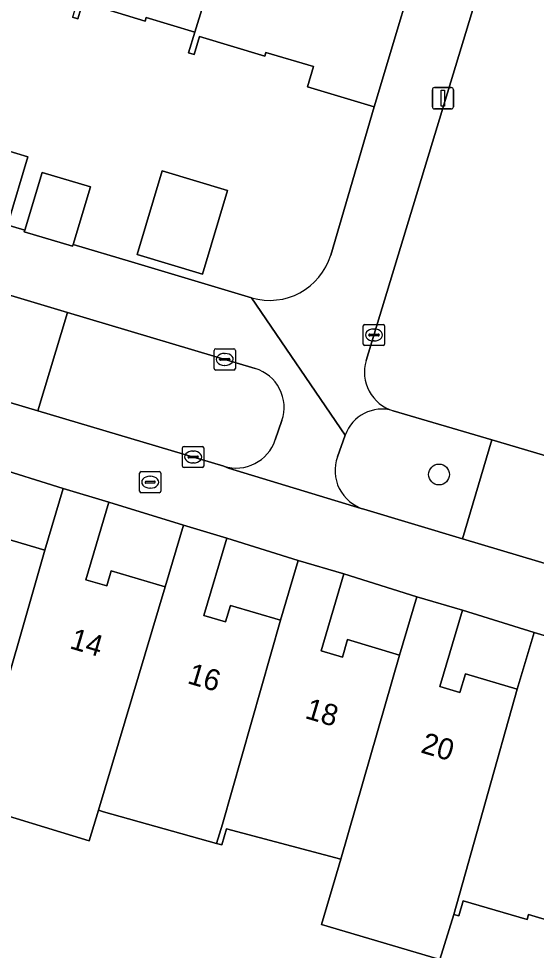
# Model space of a CAD drawing. Extents: x 162184 to 163154, y 385507 to 386516.
# Drawn here: x 162667.22 to 162691.57, y 386180.64 to 386224.51 of the extents above; entities that cross this region are included whole.
import ezdxf

# ---------------------------------------------------------------- set-up
doc = ezdxf.new("R2010")
doc.units = 0
for name, color, linetype in [('IMGEO_Boom', 7, 'Continuous'), ('IMGEO_Brandkraan', 7, 'Continuous'), ('IMGEO_Erf', 7, 'Continuous'), ('IMGEO_Groenvoorziening', 7, 'Continuous'), ('IMGEO_Kolk', 7, 'Continuous'), ('IMGEO_Lichtmast', 7, 'Continuous'), ('IMGEO_Muur', 7, 'Continuous'), ('IMGEO_Pand', 7, 'Continuous'), ('IMGEO_Pand_nummerreeks', 7, 'Continuous'), ('IMGEO_Rijbaan_lokaal_open', 7, 'Continuous'), ('IMGEO_Voetpad_open', 7, 'Continuous')]:
    doc.layers.add(name, color=color, linetype=linetype)

msp = doc.modelspace()

# ---------------------------------------------------------------- linework, layer by layer
at = {"layer": 'IMGEO_Boom'}
msp.add_circle((162686.993, 386203.046), 0.489, dxfattribs=at)
at = {"layer": 'IMGEO_Brandkraan'}
for p, q in [((162672.907, 386202.259), (162672.907, 386203.111)), ((162672.982, 386203.185), (162673.834, 386203.185)), ((162673.395, 386202.965), (162673.42, 386202.965)), ((162673.908, 386203.111), (162673.908, 386202.259)), ((162673.166, 386202.679), (162673.166, 386202.691)), ((162673.604, 386202.642), (162673.206, 386202.642)), ((162673.209, 386202.728), (162673.607, 386202.728)), ((162673.418, 386202.405), (162673.393, 386202.405)), ((162673.65, 386202.691), (162673.65, 386202.679)), ((162673.834, 386202.185), (162672.982, 386202.185))]:
    msp.add_line(p, q, dxfattribs=at)
for points in [[(162672.907, 386202.259), (162672.907, 386203.111)], [(162672.982, 386203.185), (162673.834, 386203.185)], [(162673.908, 386203.111), (162673.908, 386202.259)], [(162673.834, 386202.185), (162672.982, 386202.185)]]:
    msp.add_lwpolyline(points, dxfattribs=at)
for centre, radius, start, end in [((162672.984, 386203.109), 0.0765, 91.552, 178.448), ((162672.984, 386203.109), 0.0765, 91.552, 178.448), ((162673.832, 386203.109), 0.0765, 1.552, 88.448), ((162673.832, 386203.109), 0.0765, 1.552, 88.448), ((162673.206, 386202.688), 0.0403, 85.8775, 175.7526), ((162673.203, 386202.678), 0.0366, 178.938, 274.7102), ((162673.607, 386202.685), 0.043, 264.8664, 352.4533), ((162673.611, 386202.69), 0.0386, 1.7309, 96.639), ((162672.984, 386202.261), 0.0765, 181.552, 268.448), ((162672.984, 386202.261), 0.0765, 181.552, 268.448), ((162673.832, 386202.261), 0.0765, 271.552, 358.448), ((162673.832, 386202.261), 0.0765, 271.552, 358.448)]:
    msp.add_arc(centre, radius, start, end, dxfattribs=at)
for centre, major_axis, ratio, start_param, end_param in [((162673.394, 386202.685), (-0.387, 0.002), 0.722429, 4.712389, 7.853982), ((162673.419, 386202.685), (-0.39, 0.002), 0.717154, 1.570796, 4.712389)]:
    msp.add_ellipse(centre, major_axis=major_axis, ratio=ratio, start_param=start_param, end_param=end_param, dxfattribs=at)
at = {"layer": 'IMGEO_Erf'}
for points in [[(162609.673, 386231.789), (162618.261, 386229.221), (162619.516, 386233.282), (162623.27, 386232.189), (162622.043, 386228.107), (162647.252, 386220.589), (162647.783, 386222.491), (162651.141, 386221.554), (162650.593, 386219.592), (162667.509, 386214.547), (162668.325, 386217.27), (162670.595, 386216.59), (162669.78, 386213.87), (162672.525, 386213.051), (162678.17, 386211.368)], [(162681.897, 386213.378), (162683.948, 386220.358), (162680.8, 386221.3), (162681.084, 386222.247), (162678.853, 386222.915), (162678.799, 386222.737), (162675.72, 386223.659), (162675.469, 386222.822), (162675.215, 386222.898), (162675.507, 386223.871), (162673.224, 386224.554), (162673.176, 386224.394), (162670.232, 386225.275), (162669.999, 386224.496), (162669.754, 386224.569)], [(162693.133, 386180.547), (162693.464, 386181.665), (162691.204, 386182.336), (162691.132, 386182.093), (162688.131, 386182.984), (162687.918, 386182.267), (162687.686, 386182.336), (162687.034, 386180.211), (162681.466, 386181.862), (162682.092, 386183.975), (162682.375, 386184.93), (162676.996, 386186.36), (162676.773, 386185.611), (162676.533, 386185.682), (162671.213, 386187.169), (162670.97, 386187.241), (162670.543, 386185.797), (162664.983, 386187.492)]]:
    msp.add_lwpolyline(points, dxfattribs=at)
for points in [[(162666.725, 386214.895), (162664.116, 386215.676), (162665.047, 386218.788), (162667.657, 386218.007)], [(162675.869, 386212.483), (162672.798, 386213.402), (162673.978, 386217.342), (162677.049, 386216.423)], [(162665.894, 386203.459), (162664.788, 386199.732), (162665.828, 386199.424), (162666.058, 386200.198), (162668.454, 386199.488), (162669.313, 386202.384)], [(162671.463, 386201.746), (162670.38, 386198.094), (162671.367, 386197.801), (162671.577, 386198.51), (162674.12, 386197.756), (162674.98, 386200.654)], [(162677.007, 386200.053), (162675.926, 386196.412), (162676.95, 386196.108), (162677.18, 386196.882), (162679.539, 386196.182), (162680.375, 386199.002)], [(162682.52, 386198.365), (162681.444, 386194.738), (162682.448, 386194.44), (162682.695, 386195.273), (162685.141, 386194.547), (162685.957, 386197.294)], [(162688.098, 386196.659), (162687.03, 386193.059), (162687.972, 386192.78), (162688.232, 386193.656), (162690.669, 386192.933), (162691.463, 386195.604)]]:
    msp.add_lwpolyline(points, close=True, dxfattribs=at)
msp.add_arc((162679.025, 386214.243), 2.999, 253.4323, 343.2444, dxfattribs=at)
at = {"layer": 'IMGEO_Groenvoorziening'}
for points in [[(162669.521, 386210.679), (162651.203, 386216.166), (162643.529, 386218.419), (162642.14, 386213.753), (162651.146, 386211.101), (162668.123, 386206.04)], [(162700.454, 386196.325), (162701.908, 386200.996), (162701.811, 386201.027), (162689.472, 386204.679), (162688.104, 386200.024)]]:
    msp.add_lwpolyline(points, close=True, dxfattribs=at)
for points in [[(162678.347, 386208.035), (162669.521, 386210.679), (162668.123, 386206.04), (162676.868, 386203.433)], [(162683.454, 386201.416), (162688.104, 386200.024), (162689.472, 386204.679), (162684.836, 386206.051)], [(162679.292, 386204.673), (162679.604, 386205.587)], [(162682.581, 386204.898), (162682.213, 386203.881)]]:
    msp.add_lwpolyline(points, dxfattribs=at)
for centre, radius, start, end in [((162677.794, 386206.204), 1.913, 341.1762, 73.183), ((162684.318, 386204.282), 1.843, 73.6911, 160.471), ((162677.44, 386205.304), 1.956, 252.9905, 341.1937), ((162683.999, 386203.235), 1.899, 160.133, 253.3127)]:
    msp.add_arc(centre, radius, start, end, dxfattribs=at)
at = {"layer": 'IMGEO_Kolk'}
for p, q in [((162683.432, 386209.188), (162683.432, 386210.04)), ((162683.507, 386210.114), (162684.359, 386210.114)), ((162683.92, 386209.894), (162683.945, 386209.894)), ((162684.433, 386210.04), (162684.433, 386209.188)), ((162683.691, 386209.608), (162683.691, 386209.62)), ((162684.129, 386209.571), (162683.731, 386209.571)), ((162683.734, 386209.657), (162684.132, 386209.657)), ((162684.175, 386209.62), (162684.175, 386209.608)), ((162676.489, 386208.965), (162677.341, 386208.965)), ((162684.359, 386209.114), (162683.507, 386209.114)), ((162683.943, 386209.334), (162683.918, 386209.334)), ((162676.414, 386208.039), (162676.414, 386208.891)), ((162676.673, 386208.459), (162676.673, 386208.471)), ((162676.716, 386208.508), (162677.114, 386208.508)), ((162676.902, 386208.745), (162676.927, 386208.745)), ((162677.157, 386208.471), (162677.157, 386208.459)), ((162677.415, 386208.891), (162677.415, 386208.039)), ((162677.111, 386208.422), (162676.713, 386208.422)), ((162676.925, 386208.185), (162676.9, 386208.185)), ((162677.341, 386207.965), (162676.489, 386207.965)), ((162674.928, 386203.444), (162674.928, 386204.296)), ((162675.003, 386204.37), (162675.855, 386204.37)), ((162675.416, 386204.15), (162675.441, 386204.15)), ((162675.929, 386204.296), (162675.929, 386203.444)), ((162675.187, 386203.864), (162675.187, 386203.876)), ((162675.625, 386203.827), (162675.227, 386203.827)), ((162675.23, 386203.913), (162675.628, 386203.913)), ((162675.671, 386203.876), (162675.671, 386203.864)), ((162675.855, 386203.37), (162675.003, 386203.37)), ((162675.439, 386203.59), (162675.414, 386203.59))]:
    msp.add_line(p, q, dxfattribs=at)
for points in [[(162683.432, 386209.188), (162683.432, 386210.04)], [(162683.507, 386210.114), (162684.359, 386210.114)], [(162684.433, 386210.04), (162684.433, 386209.188)], [(162676.489, 386208.965), (162677.341, 386208.965)], [(162684.359, 386209.114), (162683.507, 386209.114)], [(162676.414, 386208.039), (162676.414, 386208.891)], [(162677.415, 386208.891), (162677.415, 386208.039)], [(162677.341, 386207.965), (162676.489, 386207.965)], [(162674.928, 386203.444), (162674.928, 386204.296)], [(162675.003, 386204.37), (162675.855, 386204.37)], [(162675.929, 386204.296), (162675.929, 386203.444)], [(162675.855, 386203.37), (162675.003, 386203.37)]]:
    msp.add_lwpolyline(points, dxfattribs=at)
for centre, radius, start, end in [((162683.509, 386210.038), 0.0765, 91.552, 178.448), ((162683.509, 386210.038), 0.0765, 91.552, 178.448), ((162684.357, 386210.038), 0.0765, 1.552, 88.448), ((162684.357, 386210.038), 0.0765, 1.552, 88.448), ((162683.731, 386209.617), 0.0403, 85.8775, 175.7526), ((162683.728, 386209.607), 0.0366, 178.938, 274.7102), ((162684.132, 386209.614), 0.043, 264.8664, 352.4533), ((162684.136, 386209.619), 0.0386, 1.7309, 96.639), ((162676.491, 386208.889), 0.0765, 91.552, 178.448), ((162676.491, 386208.889), 0.0765, 91.552, 178.448), ((162677.339, 386208.889), 0.0765, 1.552, 88.448), ((162677.339, 386208.889), 0.0765, 1.552, 88.448), ((162683.509, 386209.19), 0.0765, 181.552, 268.448), ((162683.509, 386209.19), 0.0765, 181.552, 268.448), ((162684.357, 386209.19), 0.0765, 271.552, 358.448), ((162684.357, 386209.19), 0.0765, 271.552, 358.448), ((162676.713, 386208.468), 0.0403, 85.8775, 175.7526), ((162677.118, 386208.47), 0.0386, 1.7309, 96.639), ((162676.491, 386208.041), 0.0765, 181.552, 268.448), ((162676.491, 386208.041), 0.0765, 181.552, 268.448), ((162676.71, 386208.458), 0.0366, 178.938, 274.7102), ((162677.114, 386208.465), 0.043, 264.8664, 352.4533), ((162677.339, 386208.041), 0.0765, 271.552, 358.448), ((162677.339, 386208.041), 0.0765, 271.552, 358.448), ((162675.005, 386204.294), 0.0765, 91.552, 178.448), ((162675.005, 386204.294), 0.0765, 91.552, 178.448), ((162675.853, 386204.294), 0.0765, 1.552, 88.448), ((162675.853, 386204.294), 0.0765, 1.552, 88.448), ((162675.227, 386203.873), 0.0403, 85.8775, 175.7526), ((162675.224, 386203.863), 0.0366, 178.938, 274.7102), ((162675.628, 386203.87), 0.043, 264.8664, 352.4533), ((162675.632, 386203.875), 0.0386, 1.7309, 96.639), ((162675.005, 386203.446), 0.0765, 181.552, 268.448), ((162675.005, 386203.446), 0.0765, 181.552, 268.448), ((162675.853, 386203.446), 0.0765, 271.552, 358.448), ((162675.853, 386203.446), 0.0765, 271.552, 358.448)]:
    msp.add_arc(centre, radius, start, end, dxfattribs=at)
for centre, major_axis, ratio, start_param, end_param in [((162683.919, 386209.614), (-0.387, 0.002), 0.722429, 4.712389, 7.853982), ((162683.944, 386209.614), (-0.39, 0.002), 0.717154, 1.570796, 4.712389), ((162676.901, 386208.465), (-0.387, 0.002), 0.722429, 4.712389, 7.853982), ((162676.926, 386208.465), (-0.39, 0.002), 0.717154, 1.570796, 4.712389), ((162675.415, 386203.87), (-0.387, 0.002), 0.722429, 4.712389, 7.853982), ((162675.44, 386203.87), (-0.39, 0.002), 0.717154, 1.570796, 4.712389)]:
    msp.add_ellipse(centre, major_axis=major_axis, ratio=ratio, start_param=start_param, end_param=end_param, dxfattribs=at)
at = {"layer": 'IMGEO_Lichtmast'}
for p, q in [((162686.78, 386221.259), (162687.57, 386221.259)), ((162687.57, 386221.259), (162686.78, 386221.259)), ((162686.68, 386220.359), (162686.68, 386221.159)), ((162686.68, 386221.159), (162686.68, 386220.359)), ((162687.67, 386221.159), (162687.67, 386220.359)), ((162687.67, 386220.359), (162687.67, 386221.159)), ((162687.57, 386220.259), (162686.78, 386220.259)), ((162686.78, 386220.259), (162687.57, 386220.259))]:
    msp.add_line(p, q, dxfattribs=at)
msp.add_lwpolyline([(162687.1, 386221.134), (162687.25, 386221.134), (162687.25, 386220.384), (162687.1, 386220.384), (162687.1, 386221.134)], dxfattribs=at)
for centre, start, end in [((162686.78, 386221.159), 90, 180), ((162686.78, 386221.159), 90, 180), ((162687.57, 386221.159), 0, 90), ((162687.57, 386221.159), 360, 90), ((162686.78, 386220.359), 180, 270), ((162686.78, 386220.359), 180, 270), ((162687.57, 386220.359), 270, 0), ((162687.57, 386220.359), 270, 0)]:
    msp.add_arc(centre, 0.1, start, end, dxfattribs=at)
at = {"layer": 'IMGEO_Muur'}
for points in [[(162683.948, 386220.358), (162681.897, 386213.378)], [(162678.17, 386211.368), (162672.525, 386213.051)]]:
    msp.add_lwpolyline(points, dxfattribs=at)
msp.add_arc((162679.025, 386214.243), 2.999, 253.4323, 343.2444, dxfattribs=at)
at = {"layer": 'IMGEO_Pand'}
for points in [[(162673.64, 386237.961), (162672.806, 386235.177), (162670.029, 386225.488), (162669.754, 386224.569), (162669.999, 386224.496), (162670.232, 386225.275), (162673.176, 386224.394), (162673.224, 386224.554), (162675.507, 386223.871), (162678.459, 386233.448), (162675.986, 386234.188), (162675.728, 386233.326), (162674.726, 386233.626), (162675.827, 386237.306)], [(162686.565, 386229.103), (162683.702, 386229.96), (162684.241, 386231.761), (162681.58, 386232.558), (162681.324, 386231.701), (162680.283, 386232.013), (162681.365, 386235.627), (162679.296, 386236.246), (162678.459, 386233.448), (162675.507, 386223.871), (162675.215, 386222.898), (162675.469, 386222.822), (162675.72, 386223.659), (162678.799, 386222.737), (162678.853, 386222.915), (162681.084, 386222.247), (162680.8, 386221.3), (162683.948, 386220.358)], [(162666.725, 386214.895), (162667.657, 386218.007), (162665.047, 386218.788), (162664.116, 386215.676)], [(162667.509, 386214.547), (162667.487, 386214.472), (162669.757, 386213.792), (162669.78, 386213.87), (162670.595, 386216.59), (162668.325, 386217.27)], [(162675.869, 386212.483), (162677.049, 386216.423), (162673.978, 386217.342), (162672.798, 386213.402)], [(162663.794, 386204.082), (162662.925, 386201.161), (162660.191, 386191.658), (162659.869, 386190.574), (162660.158, 386190.488), (162660.41, 386191.337), (162663.394, 386190.452), (162663.455, 386190.658), (162665.724, 386189.984), (162668.454, 386199.488), (162666.058, 386200.198), (162665.828, 386199.424), (162664.788, 386199.732), (162665.894, 386203.459)], [(162669.313, 386202.384), (162668.454, 386199.488), (162665.724, 386189.984), (162665.403, 386188.904), (162664.983, 386187.492), (162670.543, 386185.797), (162670.97, 386187.241), (162674.12, 386197.756), (162671.577, 386198.51), (162671.367, 386197.801), (162670.38, 386198.094), (162671.463, 386201.746)], [(162679.539, 386196.182), (162677.18, 386196.882), (162676.95, 386196.108), (162675.926, 386196.412), (162677.007, 386200.053), (162674.98, 386200.654), (162674.12, 386197.756), (162670.97, 386187.241), (162671.213, 386187.169), (162676.533, 386185.682), (162676.804, 386186.593)], [(162680.375, 386199.002), (162679.539, 386196.182), (162676.804, 386186.593), (162676.533, 386185.682), (162676.773, 386185.611), (162676.996, 386186.36), (162682.375, 386184.93), (162685.141, 386194.547), (162682.695, 386195.273), (162682.448, 386194.44), (162681.444, 386194.738), (162682.52, 386198.365)], [(162685.957, 386197.294), (162685.141, 386194.547), (162682.375, 386184.93), (162682.092, 386183.975), (162681.466, 386181.862), (162687.034, 386180.211), (162687.686, 386182.336), (162690.669, 386192.933), (162688.232, 386193.656), (162687.972, 386192.78), (162687.03, 386193.059), (162688.098, 386196.659)], [(162691.463, 386195.604), (162690.669, 386192.933), (162687.686, 386182.336), (162687.918, 386182.267), (162688.131, 386182.984), (162691.132, 386182.093), (162691.204, 386182.336), (162693.464, 386181.665), (162696.305, 386191.235), (162693.806, 386191.976), (162693.557, 386191.137), (162692.573, 386191.429), (162693.622, 386194.963)]]:
    msp.add_lwpolyline(points, close=True, dxfattribs=at)
at = {"layer": 'IMGEO_Rijbaan_lokaal_open'}
for points in [[(162690.136, 386230.062), (162683.566, 386208.408)], [(162684.836, 386206.051), (162689.472, 386204.679), (162701.811, 386201.027), (162701.908, 386200.996), (162706.224, 386199.597), (162706.424, 386199.519), (162708.42, 386198.954)]]:
    msp.add_lwpolyline(points, dxfattribs=at)
msp.add_arc((162685.373, 386207.861), 1.888, 163.1468, 253.4866, dxfattribs=at)
at = {"layer": 'IMGEO_Voetpad_open'}
for points in [[(162682.213, 386203.881), (162682.581, 386204.898), (162678.17, 386211.368), (162672.525, 386213.051), (162669.78, 386213.87), (162669.757, 386213.792), (162667.487, 386214.472), (162667.509, 386214.547), (162650.593, 386219.592), (162650.585, 386219.562), (162647.227, 386220.499), (162647.252, 386220.589), (162622.043, 386228.107), (162618.261, 386229.221), (162609.673, 386231.789), (162606.797, 386232.654), (162605.402, 386227.874)], [(162687.126, 386230.838), (162686.565, 386229.103), (162683.948, 386220.358), (162681.897, 386213.378)], [(162683.566, 386208.408), (162690.136, 386230.062)], [(162635.853, 386220.672), (162643.529, 386218.419), (162651.203, 386216.166), (162669.521, 386210.679), (162678.347, 386208.035)], [(162704.943, 386194.981), (162700.454, 386196.325), (162688.104, 386200.024), (162683.454, 386201.416), (162683.339, 386201.439), (162677.098, 386203.344), (162676.868, 386203.433), (162668.123, 386206.04), (162651.146, 386211.101)], [(162678.17, 386211.368), (162682.581, 386204.898)], [(162679.604, 386205.587), (162679.292, 386204.673)], [(162665.894, 386203.459), (162669.313, 386202.384), (162671.463, 386201.746), (162674.98, 386200.654), (162677.007, 386200.053), (162680.375, 386199.002), (162682.52, 386198.365), (162685.957, 386197.294), (162688.098, 386196.659), (162691.463, 386195.604), (162693.622, 386194.963), (162697.111, 386193.953), (162699.149, 386193.349), (162703.039, 386192.3)], [(162676.868, 386203.433), (162677.098, 386203.344), (162683.339, 386201.439), (162683.454, 386201.416)]]:
    msp.add_lwpolyline(points, dxfattribs=at)
for centre, radius, start, end in [((162679.025, 386214.243), 2.999, 253.4323, 343.2444), ((162677.794, 386206.204), 1.913, 341.1762, 73.183), ((162685.373, 386207.861), 1.888, 163.1468, 253.4866), ((162684.318, 386204.282), 1.843, 73.6911, 160.471), ((162677.44, 386205.304), 1.956, 252.9905, 341.1937), ((162683.999, 386203.235), 1.899, 160.133, 253.3127)]:
    msp.add_arc(centre, radius, start, end, dxfattribs=at)

# ---------------------------------------------------------------- texts
at = {"layer": 'IMGEO_Pand_nummerreeks'}
for s, rotation, p in [('14', 343.4539, (162669.574, 386194.876)), ('16', 343.453, (162675.108, 386193.232)), ('18', 343.4539, (162680.642, 386191.588)), ('20', 343.4539, (162686.088, 386189.97))]:
    msp.add_text(s, height=1, rotation=rotation, dxfattribs=at).set_placement(p)

doc.saveas('drawing.dxf')
